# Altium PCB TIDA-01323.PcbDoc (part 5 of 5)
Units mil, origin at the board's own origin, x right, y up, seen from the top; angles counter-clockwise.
Board outline 2467 x 6135 mil, 6 copper layers (Layer 1 - Top Layer, Layer 2 - GND, Layer 3 - Sensitive, Layer 4 - GND, Layer 5 - PWR, Layer 6 - Bottom Layer), stack 62.468 mil thick; 310 components, 202 nets, 881 pads, 527 vias.
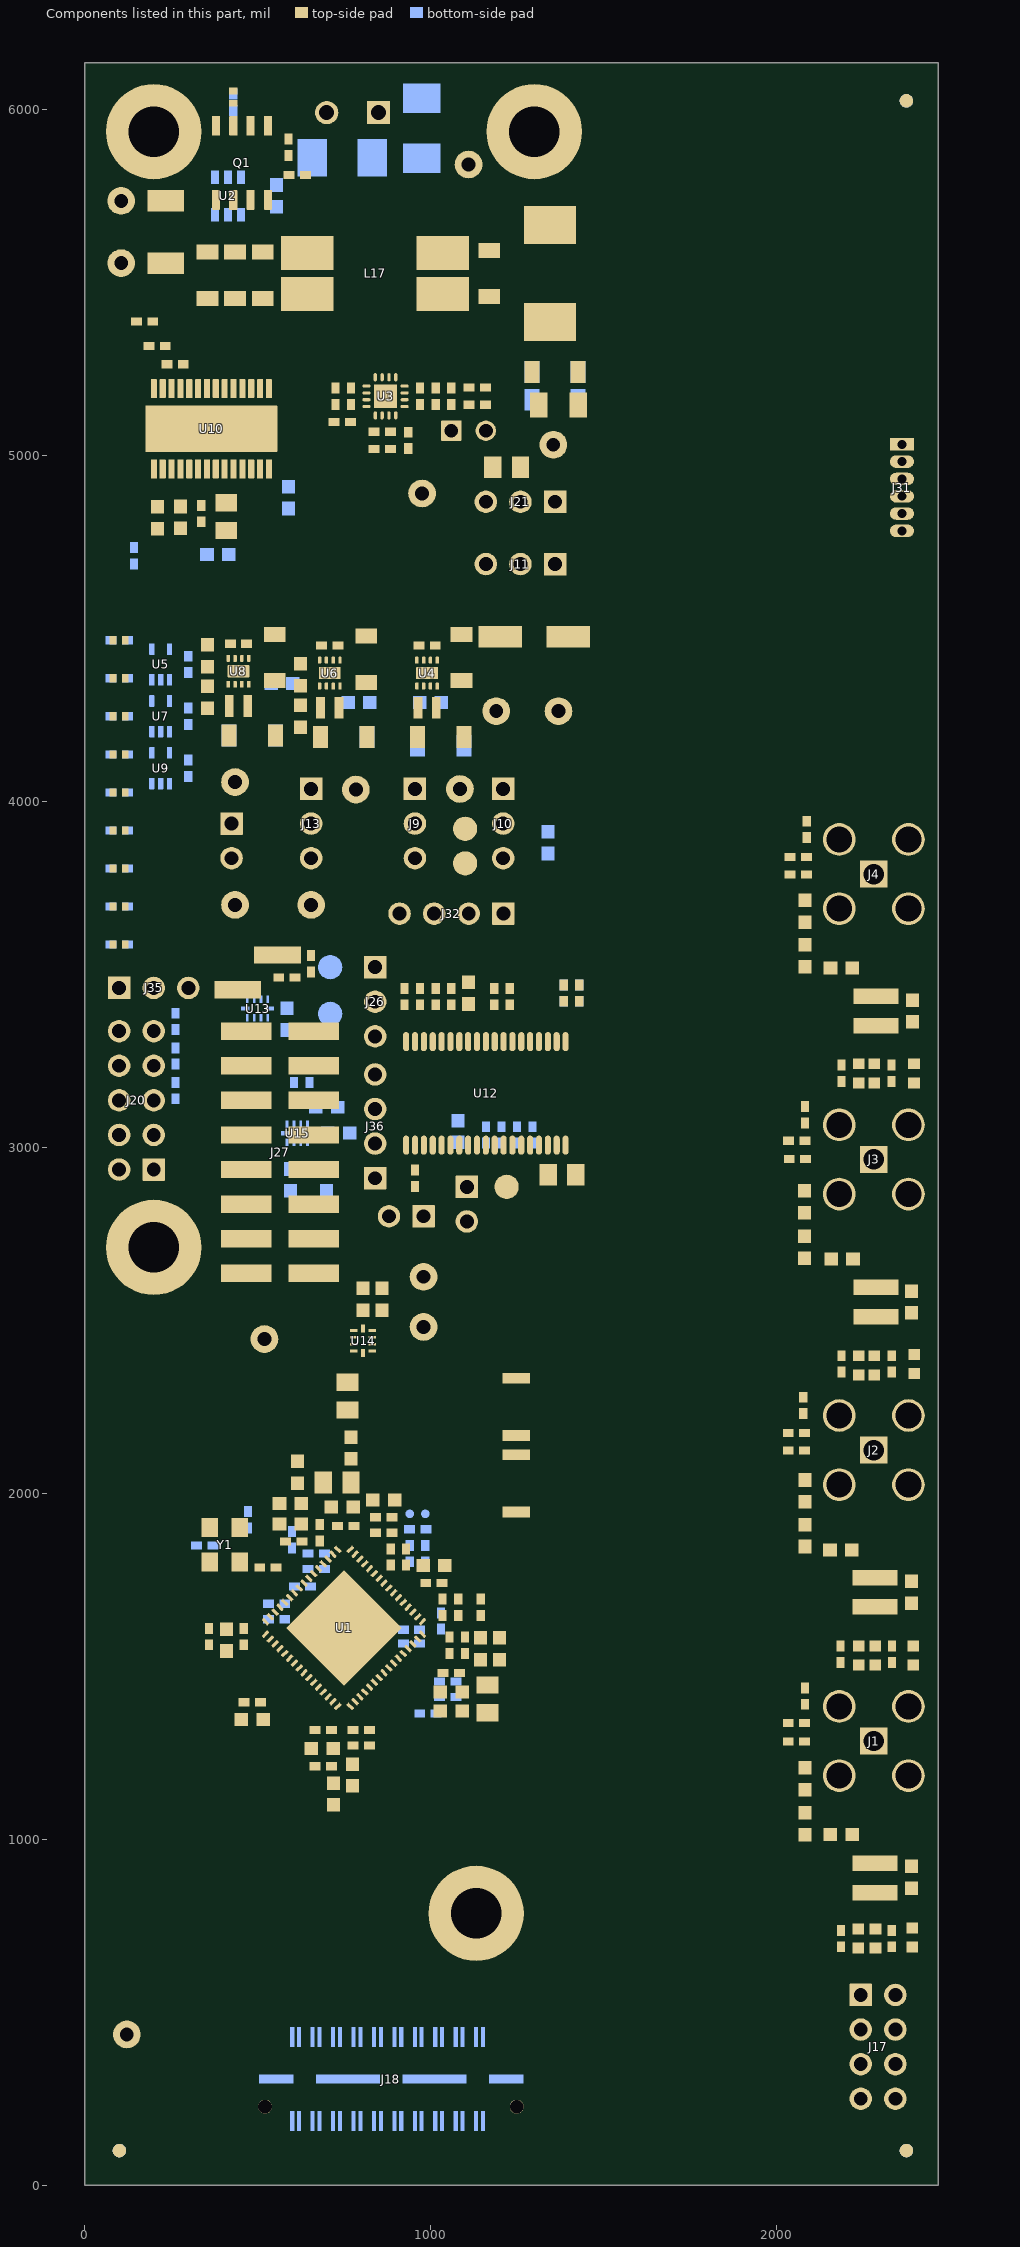
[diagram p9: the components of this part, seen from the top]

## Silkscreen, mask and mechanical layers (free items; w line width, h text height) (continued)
Drill Drawing:
  circle w10: c3128.72,1436.28 r27.63
  circle w10: c3128.72,317.4 r16.58
  circle w10: c3128.72,317.4 r27.63
  lines w10: 3101.09,414.1 3156.34,414.1 3156.34,469.35 3101.09,469.35 3101.09,414.1 ; 3101.09,593.67 3156.34,593.67 3128.72,538.42 3101.09,593.67 ; 3101.09,662.74 3156.34,662.74 3156.34,717.99 3101.09,717.99 3101.09,662.74 ; 3101.09,787.06 3128.72,800.87 3156.34,787.06 3142.53,814.68 3156.34,842.31 3128.72,828.5 3101.09,842.31 3114.9,814.68 3101.09,787.06 ; 3101.09,939 3128.72,911.38 3156.34,939 3128.72,966.63 3101.09,939 ; 3101.09,1090.95 3156.34,1090.95 3128.72,1035.7 3101.09,1090.95 ; 3101.09,1298.15 3114.9,1298.15 3128.72,1284.34 3142.53,1298.15 3156.34,1298.15 3142.53,1311.96 3156.34,1325.78 3142.53,1325.78 3128.72,1339.59 3114.9,1325.78 3101.09,1325.78 3114.9,1311.96 3101.09,1298.15 ; 3112.14,425.15 3145.29,425.15 3145.29,458.3 3112.14,458.3 3112.14,425.15 ; 3112.14,582.62 3145.29,582.62 3128.72,549.47 3112.14,582.62 ; 3112.14,798.11 3128.72,806.39 3145.29,798.11 3137.01,814.68 3145.29,831.26 3128.72,822.97 3112.14,831.26 3120.43,814.68 3112.14,798.11
  lines w12: 3051,128.16 6751.13,128.16 ; 3051,1495.68 6751.13,1495.68 ; 3388.86,3.84 3388.86,1620 ; 3720.86,3.84 3720.86,1620 ; 4357.43,3.84 4357.43,1620 ; 4616.57,3.84 4616.57,1620 ; 4991.72,3.84 4991.72,1620 ; 6184.7,3.84 6184.7,1620 ; 3051,3.84 6751.13,3.84 6751.13,1620 3051,1620 3051,3.84
  text "Symbol" at 3125.59,1532.98 h72
  text "Quantity" at 3426.16,1532.98 h72
  text "Finished Hole Size" at 3758.16,1532.98 h72
  text "Plated" at 4394.72,1532.98 h72
  text "Hole Type" at 4653.86,1532.98 h72
  text "Drill Layer Pair" at 5029.02,1532.98 h72
  text "Hole Tolerance" at 6221.99,1532.98 h72
  text "2" at 3426.16,1408.66 h60
  text "40.16mil (1.020mm)" at 3758.16,1408.66 h60
  text "NPTH" at 4394.72,1408.66 h60
  text "Round" at 4653.86,1408.66 h60
  text "Layer 1 - Top Layer - Layer 6 - Bottom Layer" at 5029.02,1408.66 h60
  text "58" at 3426.16,1284.34 h60
  text "6.00mil (0.152mm)" at 3758.16,1284.34 h60
  text "PTH" at 4394.72,1284.34 h60
  text "Round" at 4653.86,1284.34 h60
  text "Layer 1 - Top Layer - Layer 6 - Bottom Layer" at 5029.02,1284.34 h60
  text "64" at 3426.16,1160.02 h60
  text "7.87mil (0.200mm)" at 3758.16,1160.02 h60
  text "PTH" at 4394.72,1160.02 h60
  text "Round" at 4653.86,1160.02 h60
  text "Layer 1 - Top Layer - Layer 6 - Bottom Layer" at 5029.02,1160.02 h60
  text "A" at 3100.31,1150.03 h55.25
  text "397" at 3426.16,1035.7 h60
  text "10.00mil (0.254mm)" at 3758.16,1035.7 h60
  text "PTH" at 4394.72,1035.7 h60
  text "Round" at 4653.86,1035.7 h60
  text "Layer 1 - Top Layer - Layer 6 - Bottom Layer" at 5029.02,1035.7 h60
  text "8" at 3426.16,911.38 h60
  text "15.00mil (0.381mm)" at 3758.16,911.38 h60
  text "PTH" at 4394.72,911.38 h60
  text "Round" at 4653.86,911.38 h60
  text "Layer 1 - Top Layer - Layer 6 - Bottom Layer" at 5029.02,911.38 h60
  text "6" at 3426.16,787.06 h60
  text "26.00mil (0.660mm)" at 3758.16,787.06 h60
  text "PTH" at 4394.72,787.06 h60
  text "Round" at 4653.86,787.06 h60
  text "Layer 1 - Top Layer - Layer 6 - Bottom Layer" at 5029.02,787.06 h60
  text "71" at 3426.16,662.74 h60
  text "40.00mil (1.016mm)" at 3758.16,662.74 h60
  text "PTH" at 4394.72,662.74 h60
  text "Round" at 4653.86,662.74 h60
  text "Layer 1 - Top Layer - Layer 6 - Bottom Layer" at 5029.02,662.74 h60
  text "2" at 3426.16,538.42 h60
  text "43.31mil (1.100mm)" at 3758.16,538.42 h60
  text "PTH" at 4394.72,538.42 h60
  text "Round" at 4653.86,538.42 h60
  text "Layer 1 - Top Layer - Layer 6 - Bottom Layer" at 5029.02,538.42 h60
  text "4" at 3426.16,414.1 h60
  text "59.06mil (1.500mm)" at 3758.16,414.1 h60
  text "PTH" at 4394.72,414.1 h60
  text "Round" at 4653.86,414.1 h60
  text "Layer 1 - Top Layer - Layer 6 - Bottom Layer" at 5029.02,414.1 h60
  text "16" at 3426.16,289.78 h60
  text "74.80mil (1.900mm)" at 3758.16,289.78 h60
  text "PTH" at 4394.72,289.78 h60
  text "Round" at 4653.86,289.78 h60
  text "Layer 1 - Top Layer - Layer 6 - Bottom Layer" at 5029.02,289.78 h60
  text "4" at 3426.16,165.46 h60
  text "145.67mil (3.700mm)" at 3758.16,165.46 h60
  text "PTH" at 4394.72,165.46 h60
  text "Round" at 4653.86,165.46 h60
  text "Layer 1 - Top Layer - Layer 6 - Bottom Layer" at 5029.02,165.46 h60
  text "F" at 3100.31,155.46 h55.25
  text "632 Total" at 3426.16,41.14 h60
  text ".Layer_Name" at -2051,-674.49 h60
M17 Embedded Cavity:
  text ".Layer_Name" at -2051,-674.49 h60
M18 Embedded Assembly:
  text ".Layer_Name" at -2051,-674.49 h60
M19 Embedded Keepout:
  text ".Layer_Name" at -2051,-674.49 h60

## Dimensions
0,0 to 0,6135 on M2 Board Dimensions
0,0 to 2467,0 on M2 Board Dimensions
